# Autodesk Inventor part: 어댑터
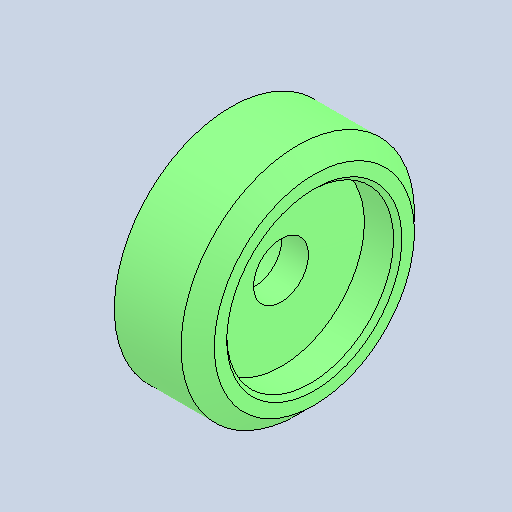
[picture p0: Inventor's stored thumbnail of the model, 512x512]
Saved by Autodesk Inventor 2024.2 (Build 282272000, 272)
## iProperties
Created: 2025-09
Part Number: 어댑터
Material: 강철, 탄소
Document SubType Name: Modeling
Designer: home
Density: 7.85 g/cm^3
Appearance: 기본값
Author: jhkim
Sending System: Autodesk Inventor 2026
Preprocessor: ST-DEVELOPER v20.1
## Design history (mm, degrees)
feature "솔리드1"
node "솔리드2"
